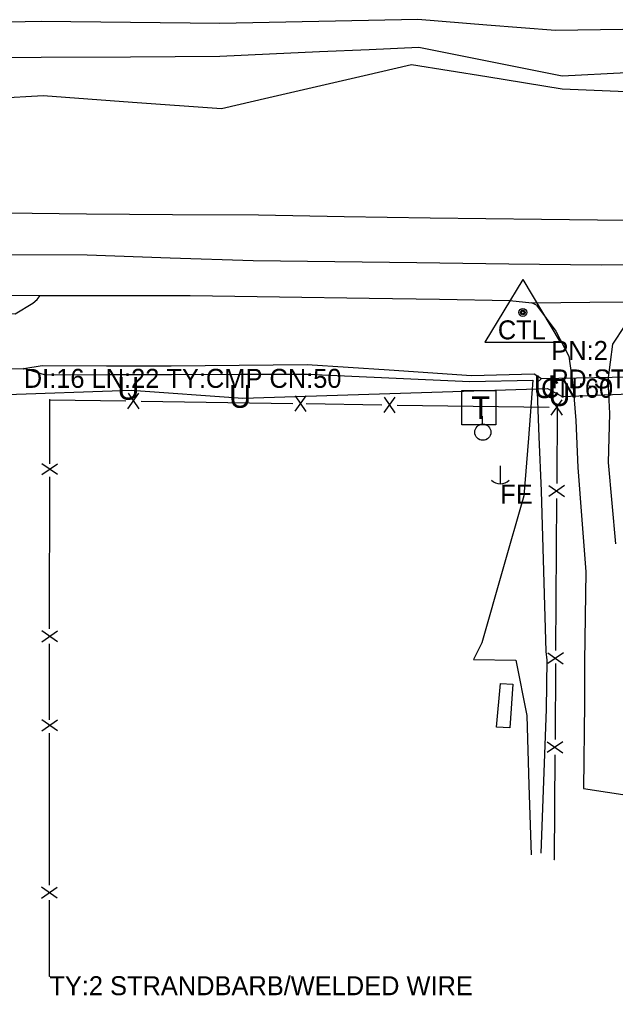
# Model space of a CAD drawing. Extents: x 1939239 to 1943096, y 531224 to 537447.
# Drawn here: x 1939856.6 to 1940013.5, y 534576.2 to 534833 of the extents above; entities that cross this region are included whole.
import ezdxf

# ---------------------------------------------------------------- set-up
doc = ezdxf.new("R2010")
doc.units = 0
for name, color, linetype in [('Default', 7, 'Continuous'), ('S_DITCHLINE', 7, 'Continuous'), ('S_DRG_PT_SYM', 7, 'Continuous'), ('S_EDGE_BITUMINOUS', 7, 'Continuous'), ('S_EDGE_CONCRETE', 7, 'Continuous'), ('S_EDGE_PAVEMENT', 7, 'Continuous'), ('S_FENCE', 7, 'Continuous'), ('S_FENCE_ANNOT', 7, 'Continuous'), ('S_MSC_PT_SYM', 7, 'Continuous'), ('S_PAVEMENT_CROWN', 7, 'Continuous'), ('S_PRIMARY_CTL', 7, 'Continuous'), ('S_PRIMARY_CTL_ANNOT', 7, 'Continuous'), ('S_SIDE_DRAIN', 7, 'Continuous'), ('S_SIDE_DRAIN_ANNOT', 7, 'Continuous'), ('S_TELEPHONE_UTILITIES', 7, 'Continuous'), ('S_UNDERGROUND_CABLE', 7, 'Continuous'), ('S_UTILITY_POLE', 7, 'Continuous'), ('S_UTILITY_POLE_ANNOT', 7, 'Continuous')]:
    doc.layers.add(name, color=color, linetype=linetype)

msp = doc.modelspace()

# ---------------------------------------------------------------- linework, layer by layer
at = {"layer": 'S_DITCHLINE'}
for points in [[(1940015.45, 534830.44), (1939997.73, 534830.12), (1939979.6, 534831.58), (1939961.47, 534833.04), (1939948.45, 534832.78), (1939935.42, 534832.53), (1939922.39, 534832.28), (1939909.37, 534832.03), (1939885.84, 534832.25), (1939862.31, 534832.48), (1939849.74, 534832.25)], [(1940016.36, 534818.98), (1939999.46, 534818.15), (1939980.61, 534821.93), (1939961.77, 534825.71), (1939948.66, 534825.1), (1939935.56, 534824.5), (1939922.45, 534823.89), (1939909.35, 534823.28), (1939885.84, 534823.17), (1939862.34, 534823.06), (1939838.43, 534822.87)], [(1940016.33, 534814.01), (1939999.5, 534814.73), (1939979.65, 534817.92), (1939959.81, 534821.11), (1939947.31, 534818.22), (1939934.8, 534815.32), (1939922.3, 534812.43), (1939909.8, 534809.53), (1939886.34, 534811.23), (1939862.88, 534812.93), (1939838.41, 534811.55)], [(1939857.78, 534741.17), (1939862.57, 534741.98), (1939879.58, 534741.93), (1939896.59, 534741.88), (1939914.48, 534742.06), (1939932.38, 534742.25), (1939953.97, 534740.81), (1939975.56, 534739.37), (1939992.12, 534739.79), (1939993.99, 534738.59), (1939992.82, 534737.42), (1939993.36, 534723.21), (1939993.9, 534709.01), (1939994.51, 534687.85), (1939995.13, 534666.7), (1939995.44, 534664.47), (1939995.22, 534651.59), (1939994.53, 534632.61), (1939993.85, 534613.63)], [(1939863.23, 534739.56), (1939857.78, 534741.17)], [(1939863.23, 534739.56), (1939879.96, 534739.58), (1939896.68, 534739.61), (1939914.57, 534739.67), (1939932.46, 534739.72), (1939953.8, 534738.76), (1939975.15, 534737.79), (1939991.77, 534738.09), (1939990.57, 534722.91), (1939989.37, 534707.73), (1939983.84, 534688.38), (1939978.31, 534669.03), (1939976.13, 534664.62), (1939987.28, 534664.48), (1939990.13, 534649.85), (1939990.72, 534631.53), (1939991.3, 534613.21)]]:
    msp.add_lwpolyline(points, dxfattribs=at)
at = {"layer": 'S_DRG_PT_SYM'}
for points in [[(1939857.77, 534741.11), (1939857.77, 534741.16), (1939857.77, 534741.11), (1939857.72, 534741.11), (1939857.77, 534741.11), (1939857.77, 534741.06), (1939857.77, 534741.11), (1939857.82, 534741.11)], [(1939993.92, 534738.5), (1939993.92, 534738.55), (1939993.92, 534738.5), (1939993.87, 534738.5), (1939993.92, 534738.5), (1939993.92, 534738.45), (1939993.92, 534738.5), (1939993.97, 534738.5)]]:
    msp.add_lwpolyline(points, dxfattribs=at)
at = {"layer": 'S_EDGE_BITUMINOUS'}
for points in [[(1939861.26, 534759.4), (1939862.09, 534760.4)], [(1939834.11, 534759.74), (1939836.09, 534758.31), (1939845.06, 534755.8), (1939855.52, 534755.62), (1939860.18, 534758.42), (1939861.26, 534759.4)], [(1939992.72, 534757.83), (1939991.5, 534758.52)], [(1939992.72, 534757.83), (1939997.75, 534751.06), (1940001.25, 534744.47), (1940002.38, 534736.23), (1940003.02, 534727.54), (1940003.54, 534715.14), (1940004.61, 534701.4), (1940005.67, 534687.66), (1940005.31, 534664.06), (1940005.32, 534653.14), (1940005.08, 534630.66), (1940017.69, 534628.78)], [(1940013.57, 534695.05), (1940011.68, 534716.45), (1940012.01, 534729.35), (1940011.58, 534738.16), (1940012.8, 534747.64), (1940016.02, 534752.51)]]:
    msp.add_lwpolyline(points, dxfattribs=at)
at = {"layer": 'S_EDGE_CONCRETE'}
msp.add_lwpolyline([(1939983.26, 534658.28), (1939986.46, 534658.16), (1939985.65, 534646.67), (1939982.21, 534646.86)], close=True, dxfattribs=at)
at = {"layer": 'S_EDGE_PAVEMENT'}
for points in [[(1939852.77, 534782.14), (1939874.25, 534781.93), (1939896.9, 534781.77), (1939919.55, 534781.6), (1939942.13, 534781.22), (1939964.7, 534780.83), (1939979.38, 534780.67), (1939994.06, 534780.51), (1940008.74, 534780.35), (1940023.42, 534780.18), (1940046.09, 534780.11), (1940068.75, 534780.04), (1940093.37, 534779.74), (1940118, 534779.43), (1940130.99, 534779.4), (1940143.99, 534779.36), (1940156.99, 534779.33), (1940169.99, 534779.3), (1940193.57, 534779.1), (1940217.16, 534778.91), (1940241.23, 534778.7), (1940265.3, 534778.5), (1940288.18, 534778.5), (1940311.06, 534778.51)], [(1939832.52, 534760.65), (1939847.3, 534760.53), (1939862.09, 534760.4)], [(1939862.09, 534760.4), (1939881.83, 534760.39), (1939901.58, 534760.37), (1939925.11, 534760.06), (1939948.63, 534759.75), (1939967.16, 534759.42), (1939985.68, 534759.08), (1939991.5, 534758.52)], [(1939991.5, 534758.52), (1940006.72, 534758.65), (1940021.94, 534758.77)]]:
    msp.add_lwpolyline(points, dxfattribs=at)
at = {"layer": 'S_FENCE'}
for p, q in [((1939885.15, 534730.62), (1939888.08, 534734.67)), ((1939885.15, 534730.62), (1939888.08, 534734.67)), ((1939885.22, 534734.72), (1939888.02, 534730.58)), ((1939885.22, 534734.72), (1939888.02, 534730.58)), ((1939929.15, 534729.95), (1939932.08, 534734.01)), ((1939929.15, 534729.95), (1939932.08, 534734.01)), ((1939929.21, 534734.05), (1939932.02, 534729.91)), ((1939929.21, 534734.05), (1939932.02, 534729.91)), ((1939952.58, 534729.6), (1939955.51, 534733.65)), ((1939952.58, 534729.6), (1939955.51, 534733.65)), ((1939952.64, 534733.69), (1939955.45, 534729.56)), ((1939952.64, 534733.69), (1939955.45, 534729.56)), ((1939996.57, 534728.93), (1939999.5, 534732.99)), ((1939996.57, 534728.93), (1939999.5, 534732.99)), ((1939996.64, 534733.03), (1939999.44, 534728.89)), ((1939996.64, 534733.03), (1939999.44, 534728.89)), ((1939866.65, 534713.28), (1939862.56, 534716.15)), ((1939862.56, 534713.28), (1939866.66, 534716.15)), ((1939866.65, 534713.28), (1939862.56, 534716.15)), ((1939862.56, 534713.28), (1939866.66, 534716.15)), ((1940000.06, 534710.38), (1939995.95, 534707.54)), ((1940000.06, 534710.38), (1939995.95, 534707.54)), ((1939995.97, 534710.41), (1940000.04, 534707.51)), ((1939995.97, 534710.41), (1940000.04, 534707.51)), ((1939866.62, 534669.28), (1939862.52, 534672.15)), ((1939862.52, 534669.28), (1939866.62, 534672.15)), ((1939866.62, 534669.28), (1939862.52, 534672.15)), ((1939862.52, 534669.28), (1939866.62, 534672.15)), ((1939999.78, 534666.38), (1939995.66, 534663.54)), ((1939999.78, 534666.38), (1939995.66, 534663.54)), ((1939995.68, 534666.41), (1939999.76, 534663.51)), ((1939995.68, 534666.41), (1939999.76, 534663.51)), ((1939862.5, 534645.85), (1939866.6, 534648.72)), ((1939862.5, 534645.85), (1939866.6, 534648.72)), ((1939866.6, 534645.85), (1939862.51, 534648.72)), ((1939866.6, 534645.85), (1939862.51, 534648.72)), ((1939999.63, 534642.95), (1939995.51, 534640.11)), ((1939999.63, 534642.95), (1939995.51, 534640.11)), ((1939995.53, 534642.97), (1939999.61, 534640.08)), ((1939995.53, 534642.97), (1939999.61, 534640.08)), ((1939866.56, 534601.85), (1939862.47, 534604.72)), ((1939862.47, 534601.85), (1939866.57, 534604.72)), ((1939866.56, 534601.85), (1939862.47, 534604.72)), ((1939862.47, 534601.85), (1939866.57, 534604.72))]:
    msp.add_line(p, q, dxfattribs=at)
for points in [[(1939864.61, 534716.15), (1939864.62, 534732.98)], [(1939864.61, 534716.15), (1939864.62, 534732.98)], [(1939864.62, 534732.98), (1939884.62, 534732.68)], [(1939864.62, 534732.98), (1939884.62, 534732.68)], [(1939888.62, 534732.62), (1939928.61, 534732.01)], [(1939888.62, 534732.62), (1939928.61, 534732.01)], [(1939932.05, 534731.96), (1939952.04, 534731.66)], [(1939932.05, 534731.96), (1939952.04, 534731.66)], [(1939956.04, 534731.59), (1939996.04, 534730.99)], [(1939956.04, 534731.59), (1939996.04, 534730.99)], [(1939998.15, 534730.96), (1939998.02, 534710.96)], [(1939998.15, 534730.96), (1939998.02, 534710.96)], [(1939864.57, 534672.72), (1939864.61, 534712.72)], [(1939864.57, 534672.72), (1939864.61, 534712.72)], [(1939997.99, 534706.96), (1939997.73, 534666.96)], [(1939997.99, 534706.96), (1939997.73, 534666.96)], [(1939864.55, 534648.72), (1939864.57, 534668.72)], [(1939864.55, 534648.72), (1939864.57, 534668.72)], [(1939997.71, 534663.53), (1939997.58, 534643.53)], [(1939997.71, 534663.53), (1939997.58, 534643.53)], [(1939864.52, 534605.28), (1939864.55, 534645.28)], [(1939864.52, 534605.28), (1939864.55, 534645.28)], [(1939997.56, 534639.53), (1939997.38, 534612.01)], [(1939997.56, 534639.53), (1939997.38, 534612.01)], [(1939864.5, 534581.28), (1939864.52, 534601.28)], [(1939864.5, 534581.28), (1939864.52, 534601.28)]]:
    msp.add_lwpolyline(points, dxfattribs=at)
at = {"layer": 'S_MSC_PT_SYM'}
for points in [[(1939864.62, 534732.98), (1939864.62, 534733.03), (1939864.62, 534732.98), (1939864.57, 534732.98), (1939864.62, 534732.98), (1939864.62, 534732.93), (1939864.62, 534732.98), (1939864.67, 534732.98)], [(1939998.15, 534730.96), (1939998.15, 534731.01), (1939998.15, 534730.96), (1939998.1, 534730.96), (1939998.15, 534730.96), (1939998.15, 534730.91), (1939998.15, 534730.96), (1939998.2, 534730.96)], [(1939997.38, 534612.01), (1939997.38, 534612.06), (1939997.38, 534612.01), (1939997.33, 534612.01), (1939997.38, 534612.01), (1939997.38, 534611.96), (1939997.38, 534612.01), (1939997.43, 534612.01)], [(1939864.5, 534581.28), (1939864.5, 534581.33), (1939864.5, 534581.28), (1939864.45, 534581.28), (1939864.5, 534581.28), (1939864.5, 534581.23), (1939864.5, 534581.28), (1939864.55, 534581.28)]]:
    msp.add_lwpolyline(points, dxfattribs=at)
at = {"layer": 'S_PAVEMENT_CROWN'}
msp.add_lwpolyline([(1939852.31, 534771.21), (1939874.42, 534771.08), (1939896.28, 534770.35), (1939918.14, 534769.62), (1939939.65, 534769.35), (1939961.17, 534769.08), (1939985.43, 534768.78), (1940009.68, 534768.48), (1940022.61, 534768.64), (1940045.69, 534768.54), (1940068.77, 534768.44), (1940093.77, 534768.28), (1940118.76, 534768.12), (1940131.55, 534768.14), (1940144.34, 534768.16), (1940157.13, 534768.18), (1940169.93, 534768.2), (1940192.98, 534768.23), (1940216.04, 534768.26), (1940240.59, 534767.93), (1940265.13, 534767.61), (1940287.69, 534767.29), (1940310.25, 534766.96)], dxfattribs=at)
at = {"layer": 'S_PRIMARY_CTL'}
for p, q in [((1939989.11, 534764.65), (1939979.08, 534748.13)), ((1939989.11, 534764.65), (1939998.94, 534748.13)), ((1939979.08, 534748.13), (1939998.94, 534748.13))]:
    msp.add_line(p, q, dxfattribs=at)
for radius in [1.04, 0.609, 0.344]:
    msp.add_circle((1939989.11, 534755.95), radius, dxfattribs=at)
at = {"layer": 'S_SIDE_DRAIN'}
for p, q in [((1939857.77, 534741.11), (1939835.87, 534740.82)), ((1940017.28, 534738.95), (1939993.92, 534738.5))]:
    msp.add_line(p, q, dxfattribs=at)
at = {"layer": 'S_TELEPHONE_UTILITIES'}
msp.add_lwpolyline([(1939973.03, 534726.37), (1939973.03, 534735.37), (1939982.03, 534735.37), (1939982.03, 534726.37)], close=True, dxfattribs=at)
at = {"layer": 'S_UNDERGROUND_CABLE'}
for p, q in [((1939845.72, 534734.04), (1939886.02, 534735.54)), ((1939886.02, 534735.54), (1939915.44, 534733.41)), ((1939915.44, 534733.41), (1939995.56, 534735.96)), ((1939995.56, 534735.96), (1939999.47, 534733.87)), ((1939999.47, 534733.87), (1940027.08, 534734.89))]:
    msp.add_line(p, q, dxfattribs=at)
at = {"layer": 'S_UTILITY_POLE'}
for p, q in [((1939978.46, 534726.57), (1939978.46, 534728.68)), ((1939983.14, 534715.58), (1939983.14, 534710.85))]:
    msp.add_line(p, q, dxfattribs=at)
msp.add_circle((1939978.58, 534724.43), 2.13, dxfattribs=at)
msp.add_arc((1939983.2, 534714.28), 3.41, 226.3972, 313.6028, dxfattribs=at)

# ---------------------------------------------------------------- texts
at = {"layer": 'Default'}
for p in [(1939991.93, 534733.42), (1939882.39, 534732.99), (1939911.81, 534730.86), (1939995.84, 534731.32)]:
    msp.add_text('U', height=6, dxfattribs=at).set_placement(p)
at = {"layer": 'S_FENCE_ANNOT'}
msp.add_text('TY:2 STRANDBARB/WELDED WIRE', height=5, dxfattribs=at).set_placement((1939864.5, 534576.28))
at = {"layer": 'S_PRIMARY_CTL'}
msp.add_text('CTL', height=5, dxfattribs=at).set_placement((1939982.53, 534748.87))
at = {"layer": 'S_PRIMARY_CTL_ANNOT'}
for s, p in [('PN:2', (1939996.61, 534743.45)), ('PD:STANDARD ARDOT CAP STAMPED PN:2', (1939996.61, 534735.95))]:
    msp.add_text(s, height=5, dxfattribs=at).set_placement(p)
at = {"layer": 'S_SIDE_DRAIN_ANNOT'}
for s, p in [('DI:16 LN:22 TY:CMP CN:50', (1939857.77, 534736.11)), ('CN:60', (1939993.92, 534733.5))]:
    msp.add_text(s, height=5, dxfattribs=at).set_placement(p)
at = {"layer": 'S_TELEPHONE_UTILITIES'}
msp.add_text('T', height=6, dxfattribs=at).set_placement((1939975.59, 534727.87))
at = {"layer": 'S_UTILITY_POLE_ANNOT'}
msp.add_text('FE', height=5, dxfattribs=at).set_placement((1939983.16, 534705.64))

doc.saveas('drawing.dxf')
